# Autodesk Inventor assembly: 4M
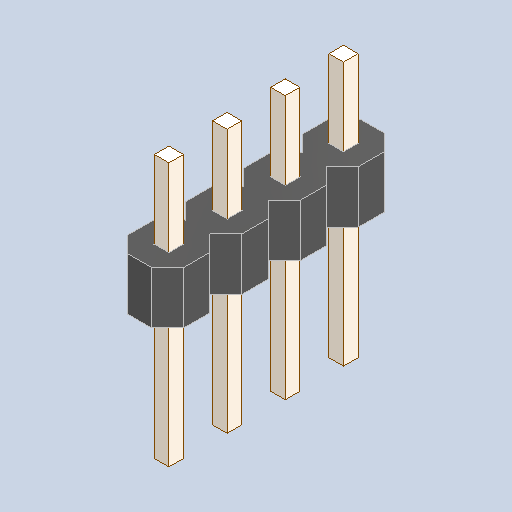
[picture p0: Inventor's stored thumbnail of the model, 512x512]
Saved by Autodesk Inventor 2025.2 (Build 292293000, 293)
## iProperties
Created: 2025-04
Part Number: 4M
Description: PART--DESC
Document SubType Name: Assembly
Designer: BennF
Author: BennF
Revision Number: NONE
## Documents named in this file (3)
- C:\Users\BennF\Nextcloud\Benutzer\CNC JarBeRi\existing parts\Electronics\RepRap A4988 Shied (USE WITHOUT ARDUINO)\reprap-a4988-1.snapshot.1\RepRap\RepRap\4M_4.iam
- C:\Users\BennF\Nextcloud\Benutzer\CNC JarBeRi\existing parts\Electronics\RepRap A4988 Shied (USE WITHOUT ARDUINO)\reprap-a4988-1.snapshot.1\RepRap\RepRap\4M Geometry.ipt
- C:\Users\BennF\Nextcloud\Benutzer\CNC JarBeRi\existing parts\Electronics\RepRap A4988 Shied (USE WITHOUT ARDUINO)\reprap-a4988-1.snapshot.1\RepRap\RepRap\Pin5.ipt
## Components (2 placed, 2 different names)
1. 4M Geometry
2. Pin5
